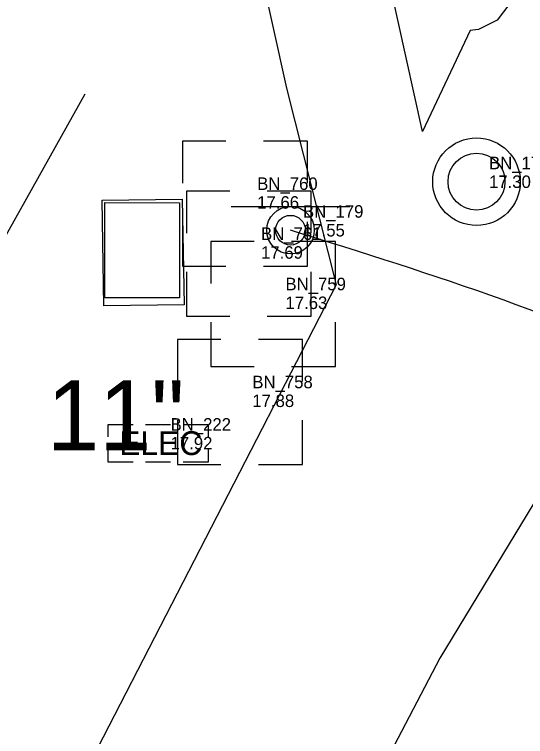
# Model space of a CAD drawing. Extents: x 509744 to 512285, y 1314862 to 1316822.
# Drawn here: x 511108.69 to 511129.12, y 1315537.93 to 1315566.79 of the extents above; entities that cross this region are included whole.
import ezdxf

# ---------------------------------------------------------------- set-up
doc = ezdxf.new("R2010")
doc.units = 0
for name, color, linetype in [('Bollard_ep', 7, 'Continuous'), ('ConcSlabs_ep', 7, 'Continuous'), ('MeterElec_ep', 7, 'Continuous'), ('PullBox_ep', 7, 'Continuous'), ('SidewalkBack_ep', 7, 'Continuous'), ('SidewalkFront_ep', 7, 'Continuous'), ('SignSingle_ep', 7, 'Continuous'), ('Slopes_ep', 7, 'Continuous'), ('TextElevLabel', 7, 'Continuous'), ('TextPtLabel', 7, 'Continuous'), ('TextTopoLabel_ep', 7, 'Continuous'), ('TreeLineScatter_ep', 7, 'Continuous')]:
    doc.layers.add(name, color=color, linetype=linetype)

msp = doc.modelspace()

# ---------------------------------------------------------------- linework, layer by layer
at = {"layer": 'Bollard_ep'}
for radius in [1.75, 1.75, 1.137]:
    msp.add_circle((511127.16, 1315560.104), radius, dxfattribs=at)
at = {"layer": 'ConcSlabs_ep'}
msp.add_lwpolyline([(511115.285, 1315559.266), (511115.28, 1315555.465), (511112.3, 1315555.469), (511112.305, 1315559.27)], close=True, dxfattribs=at)
at = {"layer": 'MeterElec_ep'}
for points in [[(511112.429, 1315549.905), (511112.429, 1315550.407), (511113.429, 1315550.407)], [(511113.929, 1315550.407), (511114.929, 1315550.407)], [(511115.429, 1315550.407), (511116.429, 1315550.407), (511116.429, 1315549.905)], [(511113.429, 1315548.903), (511112.429, 1315548.903), (511112.429, 1315549.405)], [(511116.429, 1315549.405), (511116.429, 1315548.903), (511115.429, 1315548.903)], [(511114.929, 1315548.903), (511113.929, 1315548.903)]]:
    msp.add_lwpolyline(points, dxfattribs=at)
at = {"layer": 'PullBox_ep'}
for points in [[(511117.138, 1315561.727), (511115.405, 1315561.727), (511115.405, 1315560.052)], [(511120.4, 1315560.052), (511120.4, 1315561.727), (511118.638, 1315561.727)], [(511117.292, 1315559.728), (511115.559, 1315559.728), (511115.559, 1315558.052)], [(511120.554, 1315558.052), (511120.554, 1315559.728), (511118.792, 1315559.728)], [(511115.405, 1315558.5), (511115.405, 1315556.727)], [(511118.638, 1315556.727), (511120.4, 1315556.727), (511120.4, 1315558.5)], [(511118.268, 1315557.717), (511116.534, 1315557.717), (511116.534, 1315556.042)], [(511121.529, 1315556.042), (511121.529, 1315557.717), (511119.768, 1315557.717)], [(511115.405, 1315556.727), (511117.138, 1315556.727)], [(511115.559, 1315556.5), (511115.559, 1315554.728)], [(511118.792, 1315554.728), (511120.554, 1315554.728), (511120.554, 1315556.5)], [(511115.559, 1315554.728), (511117.292, 1315554.728)], [(511116.534, 1315554.49), (511116.534, 1315552.717)], [(511119.768, 1315552.717), (511121.529, 1315552.717), (511121.529, 1315554.49)], [(511116.943, 1315553.802), (511115.21, 1315553.802), (511115.21, 1315552.126)], [(511120.205, 1315552.126), (511120.205, 1315553.802), (511118.443, 1315553.802)], [(511116.534, 1315552.717), (511118.268, 1315552.717)], [(511115.21, 1315550.574), (511115.21, 1315548.802)], [(511118.443, 1315548.802), (511120.205, 1315548.802), (511120.205, 1315550.574)], [(511115.21, 1315548.802), (511116.943, 1315548.802)]]:
    msp.add_lwpolyline(points, dxfattribs=at)
at = {"layer": 'SidewalkBack_ep'}
msp.add_lwpolyline([(511071.185, 1315587.148), (511087.197, 1315586.758), (511091.874, 1315586.203), (511099.066, 1315584.297), (511104.18, 1315582.43), (511112.099, 1315578.705), (511114.869, 1315577.025), (511116.308, 1315575.647), (511117.403, 1315573.589), (511119.56, 1315563.84), (511121.553, 1315555.989), (511110.654, 1315534.839), (511105.62, 1315524.31), (511101.435, 1315512.254), (511098.321, 1315500.871), (511095.973, 1315488.087), (511094.342, 1315479.204), (511093.897, 1315474.896), (511092.859, 1315460.936), (511092.65, 1315449.974), (511093.658, 1315432.038), (511094.596, 1315420.636), (511096.358, 1315412.043), (511100.175, 1315396.275)], dxfattribs=at)
at = {"layer": 'SidewalkFront_ep'}
msp.add_line((511126.911, 1315566.152), (511124.996, 1315562.114), dxfattribs=at)
for points in [[(511124.996, 1315562.114), (511122.076, 1315575.311), (511120.292, 1315578.662), (511117.893, 1315580.958), (511114.44, 1315583.054), (511106.084, 1315586.984), (511100.548, 1315589.006), (511092.802, 1315591.058), (511087.549, 1315591.682), (511072.334, 1315592.002)], [(511128.367, 1315568.838), (511128.624, 1315568.045), (511128.487, 1315567.223), (511127.988, 1315566.555), (511127.239, 1315566.192), (511126.911, 1315566.152)], [(511137.924, 1315560.913), (511136.191, 1315559.712), (511133.471, 1315555.426), (511131.191, 1315550.14), (511125.7, 1315541.067), (511116.983, 1315524.407), (511111.241, 1315509.731), (511108.39, 1315498.516), (511105.31, 1315481.862), (511102.749, 1315446.599), (511103.628, 1315432.89), (511105.444, 1315418.36), (511109.627, 1315400.966), (511116.005, 1315377.966), (511119.169, 1315363.32), (511121.337, 1315347.618), (511123.315, 1315325.765), (511122.963, 1315313.404), (511122.589, 1315300.269), (511120.444, 1315286.278), (511115.953, 1315254.153), (511113.828, 1315237.147)]]:
    msp.add_lwpolyline(points, dxfattribs=at)
at = {"layer": 'SignSingle_ep'}
msp.add_line((511117.348, 1315559.117), (511122.098, 1315559.117), dxfattribs=at)
for radius in [0.95, 0.594]:
    msp.add_circle((511119.723, 1315558.167), radius, dxfattribs=at)
at = {"layer": 'Slopes_ep'}
msp.add_lwpolyline([(511112.189, 1315559.373), (511115.396, 1315559.406), (511115.473, 1315555.179), (511112.266, 1315555.147)], close=True, dxfattribs=at)
at = {"layer": 'TextTopoLabel_ep'}
msp.add_spline([(511148.769, 1315543.581), (511136.342, 1315551.865), (511119.723, 1315558.167)], degree=3, dxfattribs=at)
at = {"layer": 'TreeLineScatter_ep'}
msp.add_lwpolyline([(511111.506, 1315563.602), (511096.234, 1315536.329), (511090.02, 1315515.279), (511084.074, 1315489.783), (511084.235, 1315476.874), (511083.217, 1315455.396), (511084.77, 1315425.615), (511085.778, 1315406.287), (511088.757, 1315390.348), (511094.715, 1315358.467), (511100.395, 1315328.074), (511103.764, 1315305.925), (511096.854, 1315270.306), (511095.139, 1315241.489), (511093.264, 1315230.991)], dxfattribs=at)

# ---------------------------------------------------------------- texts
at = {"layer": 'MeterElec_ep'}
msp.add_text('ELEC', height=0.95, dxfattribs=at).set_placement((511112.877, 1315549.182))
at = {"layer": 'TextElevLabel'}
for s, p in [('17.30', (511127.66, 1315559.854)), ('17.66', (511118.392, 1315559.027)), ('17.55', (511120.223, 1315557.917)), ('17.69', (511118.546, 1315557.028)), ('17.63', (511119.522, 1315555.017)), ('17.88', (511118.197, 1315551.102)), ('17.92', (511114.929, 1315549.407))]:
    msp.add_text(s, height=0.5, dxfattribs=at).set_placement(p)
at = {"layer": 'TextPtLabel'}
for s, p in [('BN_174', (511127.66, 1315560.604)), ('BN_760', (511118.392, 1315559.777)), ('BN_179', (511120.223, 1315558.667)), ('BN_761', (511118.546, 1315557.778)), ('BN_759', (511119.522, 1315555.767)), ('BN_758', (511118.197, 1315551.852)), ('BN_222', (511114.929, 1315550.157))]:
    msp.add_text(s, height=0.5, dxfattribs=at).set_placement(p)
at = {"layer": 'TextTopoLabel_ep'}
msp.add_text('11"', height=2.8, dxfattribs=at).set_placement((511109.989, 1315549.372))

doc.saveas('drawing.dxf')
